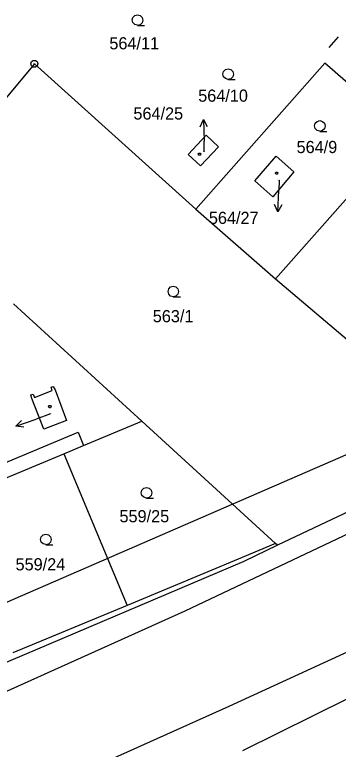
# Model space of a CAD drawing. Extents: x -759699 to -757730, y -1172308 to -1170857.
# Drawn here: x -759096.2 to -759051, y -1171620.5 to -1171517.7 of the extents above; entities that cross this region are included whole.
import ezdxf

# ---------------------------------------------------------------- set-up
doc = ezdxf.new("R2010")
doc.units = 0
for name, color, linetype in [('Vrstva 1', 7, 'Continuous'), ('Vrstva 12', 7, 'Continuous'), ('Vrstva 2', 7, 'Continuous'), ('Vrstva 3', 7, 'Continuous'), ('Vrstva 4', 7, 'Continuous'), ('Vrstva 5', 7, 'Continuous'), ('Vrstva 6', 7, 'Continuous'), ('Vrstva 7', 7, 'Continuous'), ('Vrstva 8', 7, 'Continuous')]:
    doc.layers.add(name, color=color, linetype=linetype)

msp = doc.modelspace()

# ---------------------------------------------------------------- linework, layer by layer
at = {"layer": 'Vrstva 1'}
for p, q in [((-759052.28, -1171522.29), (-759050.96, -1171520.79)), ((-759052.28, -1171522.29), (-759052.28, -1171522.29)), ((-759093.5, -1171524.55), (-759106.82, -1171540.51)), ((-759093.5, -1171524.55), (-759093.5, -1171524.55)), ((-759093.5, -1171524.55), (-759093.5, -1171524.55)), ((-759082.22, -1171534.73), (-759093.5, -1171524.55)), ((-759052.86, -1171524.45), (-759070.93, -1171544.91)), ((-759052.86, -1171524.45), (-759052.86, -1171524.45)), ((-759041.76, -1171534.25), (-759052.86, -1171524.45)), ((-759071.97, -1171537.23), (-759069.48, -1171534.54)), ((-759069.48, -1171534.54), (-759067.75, -1171536.16)), ((-759059.77, -1171554.66), (-759041.76, -1171534.25)), ((-759070.93, -1171544.91), (-759082.22, -1171534.73)), ((-759082.22, -1171534.73), (-759082.22, -1171534.73)), ((-759067.75, -1171536.16), (-759070.25, -1171538.84)), ((-759070.25, -1171538.84), (-759071.97, -1171537.23)), ((-759062.67, -1171540.93), (-759059.69, -1171537.49)), ((-759059.69, -1171537.49), (-759057.21, -1171539.69)), ((-759057.21, -1171539.69), (-759060.15, -1171543.16)), ((-759060.15, -1171543.16), (-759062.67, -1171540.93)), ((-759070.93, -1171544.91), (-759059.77, -1171554.66)), ((-759059.77, -1171554.66), (-759047.8, -1171564.8)), ((-759078.48, -1171574.58), (-759096.41, -1171558.16)), ((-759093.48, -1171571.26), (-759090.99, -1171570.3)), ((-759091.17, -1171569.82), (-759090.85, -1171569.7)), ((-759090.99, -1171570.3), (-759091.17, -1171569.82)), ((-759090.85, -1171569.7), (-759090.61, -1171570.18)), ((-759090.61, -1171570.18), (-759088.99, -1171574.5)), ((-759093.98, -1171570.91), (-759093.67, -1171570.79)), ((-759093.87, -1171571.4), (-759093.98, -1171570.91)), ((-759092.17, -1171575.7), (-759093.87, -1171571.4)), ((-759093.67, -1171570.79), (-759093.48, -1171571.26)), ((-759088.99, -1171574.5), (-759092.17, -1171575.7)), ((-759086.62, -1171577.97), (-759078.48, -1171574.58)), ((-759078.48, -1171574.58), (-759059.77, -1171591.7)), ((-759103.07, -1171582.66), (-759087.39, -1171576.13)), ((-759087.39, -1171576.13), (-759086.62, -1171577.97)), ((-759089.39, -1171579.13), (-759086.62, -1171577.97)), ((-759105.35, -1171585.79), (-759089.39, -1171579.13)), ((-759089.39, -1171579.13), (-759080.54, -1171600.36)), ((-759046.04, -1171585.58), (-759059.5, -1171591.95)), ((-759059.77, -1171591.7), (-759064.42, -1171593.64)), ((-759059.5, -1171591.95), (-759064.19, -1171594.2)), ((-759059.5, -1171591.95), (-759059.77, -1171591.7)), ((-759064.19, -1171594.2), (-759118.37, -1171617.22)), ((-759064.42, -1171593.64), (-759080.54, -1171600.36)), ((-759080.54, -1171600.36), (-759096.5, -1171607.02)), ((-759064.34, -1171620.67), (-759049.49, -1171613.28))]:
    msp.add_line(p, q, dxfattribs=at)
at = {"layer": 'Vrstva 12'}
for p, q in [((-759071.97, -1171537.23), (-759069.48, -1171534.54)), ((-759069.48, -1171534.54), (-759067.75, -1171536.16)), ((-759067.75, -1171536.16), (-759070.25, -1171538.84)), ((-759070.25, -1171538.84), (-759071.97, -1171537.23)), ((-759062.67, -1171540.93), (-759059.69, -1171537.49)), ((-759059.69, -1171537.49), (-759057.21, -1171539.69)), ((-759057.21, -1171539.69), (-759060.15, -1171543.16)), ((-759060.15, -1171543.16), (-759062.67, -1171540.93)), ((-759093.48, -1171571.26), (-759090.99, -1171570.3)), ((-759091.17, -1171569.82), (-759090.85, -1171569.7)), ((-759090.99, -1171570.3), (-759091.17, -1171569.82)), ((-759090.85, -1171569.7), (-759090.61, -1171570.18)), ((-759090.61, -1171570.18), (-759088.99, -1171574.5)), ((-759093.98, -1171570.91), (-759093.67, -1171570.79)), ((-759093.87, -1171571.4), (-759093.98, -1171570.91)), ((-759092.17, -1171575.7), (-759093.87, -1171571.4)), ((-759093.67, -1171570.79), (-759093.48, -1171571.26)), ((-759088.99, -1171574.5), (-759092.17, -1171575.7))]:
    msp.add_line(p, q, dxfattribs=at)
at = {"layer": 'Vrstva 3'}
for points in [[(-759079.07, -1171519.16), (-759079.45, -1171519.06), (-759079.72, -1171518.79), (-759079.82, -1171518.42), (-759079.72, -1171518.05), (-759079.45, -1171517.78), (-759079.08, -1171517.68), (-759078.71, -1171517.78), (-759078.44, -1171518.05), (-759078.34, -1171518.43), (-759078.44, -1171518.81), (-759078.71, -1171519.08), (-759079.09, -1171519.18), (-759078.09, -1171519.18)], [(-759066.38, -1171526.73), (-759066.76, -1171526.63), (-759067.03, -1171526.36), (-759067.13, -1171525.99), (-759067.03, -1171525.62), (-759066.76, -1171525.35), (-759066.39, -1171525.25), (-759066.02, -1171525.35), (-759065.75, -1171525.62), (-759065.65, -1171526), (-759065.75, -1171526.38), (-759066.02, -1171526.65), (-759066.4, -1171526.75), (-759065.4, -1171526.75)], [(-759053.56, -1171533.99), (-759053.94, -1171533.89), (-759054.21, -1171533.62), (-759054.31, -1171533.25), (-759054.21, -1171532.88), (-759053.94, -1171532.61), (-759053.57, -1171532.51), (-759053.2, -1171532.61), (-759052.93, -1171532.88), (-759052.83, -1171533.26), (-759052.93, -1171533.64), (-759053.2, -1171533.91), (-759053.58, -1171534.01), (-759052.58, -1171534.01)], [(-759074.06, -1171557.17), (-759074.44, -1171557.07), (-759074.71, -1171556.8), (-759074.81, -1171556.43), (-759074.71, -1171556.06), (-759074.44, -1171555.79), (-759074.07, -1171555.69), (-759073.7, -1171555.79), (-759073.43, -1171556.06), (-759073.33, -1171556.44), (-759073.43, -1171556.82), (-759073.7, -1171557.09), (-759074.08, -1171557.19), (-759073.08, -1171557.19)], [(-759077.81, -1171585.33), (-759078.19, -1171585.23), (-759078.46, -1171584.96), (-759078.56, -1171584.59), (-759078.46, -1171584.22), (-759078.19, -1171583.95), (-759077.82, -1171583.85), (-759077.45, -1171583.95), (-759077.18, -1171584.22), (-759077.08, -1171584.6), (-759077.18, -1171584.98), (-759077.45, -1171585.25), (-759077.83, -1171585.35), (-759076.83, -1171585.35)], [(-759091.88, -1171591.86), (-759092.26, -1171591.76), (-759092.53, -1171591.49), (-759092.63, -1171591.12), (-759092.53, -1171590.75), (-759092.26, -1171590.48), (-759091.89, -1171590.38), (-759091.52, -1171590.48), (-759091.25, -1171590.75), (-759091.15, -1171591.13), (-759091.25, -1171591.51), (-759091.52, -1171591.78), (-759091.9, -1171591.88), (-759090.9, -1171591.88)]]:
    msp.add_lwpolyline(points, dxfattribs=at)
at = {"layer": 'Vrstva 4'}
for p, q in [((-759024.83, -1171578.53), (-759072.45, -1171601.16)), ((-759018.34, -1171592.41), (-759066.3, -1171614.53)), ((-759072.45, -1171601.16), (-759121.76, -1171623.41)), ((-759066.3, -1171614.53), (-759116.88, -1171637.18))]:
    msp.add_line(p, q, dxfattribs=at)
at = {"layer": 'Vrstva 5'}
for points in [[(-759070.31, -1171537.04), (-759070.22, -1171537.19), (-759070.31, -1171537.34), (-759070.49, -1171537.34), (-759070.58, -1171537.19), (-759070.49, -1171537.04)], [(-759059.53, -1171539.72), (-759059.44, -1171539.87), (-759059.53, -1171540.02), (-759059.71, -1171540.02), (-759059.8, -1171539.87), (-759059.71, -1171539.72)], [(-759091.23, -1171572.39), (-759091.14, -1171572.54), (-759091.23, -1171572.69), (-759091.41, -1171572.69), (-759091.5, -1171572.54), (-759091.41, -1171572.39)]]:
    msp.add_lwpolyline(points, close=True, dxfattribs=at)
at = {"layer": 'Vrstva 6'}
msp.add_line((-759105.39, -1171603.36), (-759038.87, -1171574.49), dxfattribs=at)
at = {"layer": 'Vrstva 7'}
for p, q in [((-759069.83, -1171532.361), (-759069.77, -1171535.36)), ((-759069.74, -1171536.87), (-759069.77, -1171535.36)), ((-759059.28, -1171540.85), (-759059.33, -1171542.27)), ((-759059.446, -1171545.268), (-759059.33, -1171542.27)), ((-759091.25, -1171573.56), (-759093.26, -1171574.28)), ((-759096.087, -1171575.284), (-759093.26, -1171574.28))]:
    msp.add_line(p, q, dxfattribs=at)
for points in [[(-759070.31, -1171533.37), (-759069.83, -1171532.361), (-759069.31, -1171533.35)], [(-759058.908, -1171544.288), (-759059.446, -1171545.268), (-759059.907, -1171544.249)], [(-759094.977, -1171575.42), (-759096.087, -1171575.284), (-759095.312, -1171574.478)]]:
    msp.add_lwpolyline(points, dxfattribs=at)
at = {"layer": 'Vrstva 8'}
msp.add_line((-759093.62, -1171524.55), (-759093.38, -1171524.55), dxfattribs=at)
msp.add_lwpolyline([(-759093.35, -1171524.07), (-759093.1, -1171524.25), (-759093, -1171524.54), (-759093.1, -1171524.83), (-759093.35, -1171525.01), (-759093.66, -1171525.01), (-759093.91, -1171524.83), (-759094.01, -1171524.54), (-759093.91, -1171524.25), (-759093.66, -1171524.07)], close=True, dxfattribs=at)

# ---------------------------------------------------------------- texts
at = {"layer": 'Vrstva 2'}
for s, height, p in [('564/11', 1.7, (-759083.013, -1171522.53)), ('564/10', 1.7, (-759070.588, -1171529.86)), ('564/9', 1.7, (-759056.83, -1171537.05)), ('564/25', 0.1, (-759069.992, -1171536.87)), ('564/27', 0.1, (-759059.527, -1171540.85)), ('563/1', 1.7, (-759076.939, -1171560.73)), ('559/29', 0.1, (-759091.502, -1171573.56)), ('559/25', 1.7, (-759081.597, -1171588.73)), ('559/24', 1.7, (-759096.13, -1171595.46))]:
    msp.add_text(s, height=height, dxfattribs=at).set_placement(p)
at = {"layer": 'Vrstva 7'}
for s, p in [('564/25', (-759079.648, -1171532.36)), ('564/27', (-759069.094, -1171546.97))]:
    msp.add_text(s, height=1.7, dxfattribs=at).set_placement(p)

doc.saveas('drawing.dxf')
